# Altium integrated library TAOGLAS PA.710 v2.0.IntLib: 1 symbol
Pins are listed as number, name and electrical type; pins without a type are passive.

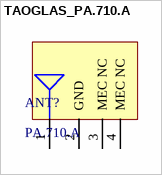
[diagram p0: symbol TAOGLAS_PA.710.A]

## TAOGLAS_PA.710.A
designator ANT?, comment PA.710.A
Warrior LTE/Cellular SMD Antenna for 4G/3G/2G Applications; ComponentLibStatus: Created; MFG: Taoglas; Temp_High: +85C; Temp_Low: -40C
footprint TAOGLAS_PA.710.A (Warrior LTE/Cellular SMD Antenna for 4G/3G/2G Applications)
pins: 1 RF OUT, 2 GND, 3 MEC NC, 4 MEC NC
